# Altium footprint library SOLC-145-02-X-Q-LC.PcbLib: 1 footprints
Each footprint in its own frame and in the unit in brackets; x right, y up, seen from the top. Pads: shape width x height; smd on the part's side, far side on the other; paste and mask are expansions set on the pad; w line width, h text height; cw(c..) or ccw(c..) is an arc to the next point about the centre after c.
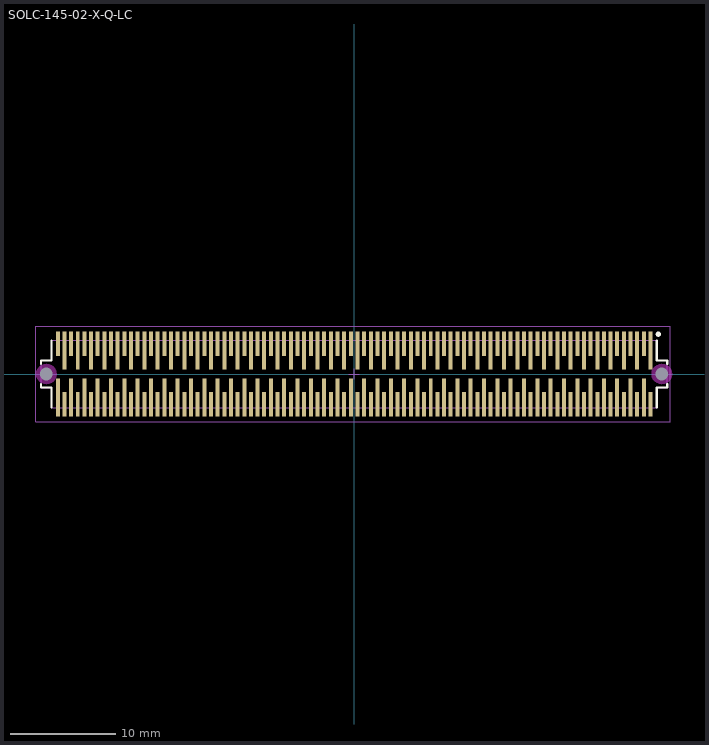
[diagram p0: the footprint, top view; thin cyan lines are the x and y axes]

## SOLC-145-02-X-Q-LC [mm] "1.27mm pitch, 180 pin, socket strip; 4 rows, w/locking clips, SMT"
height 4.62
pads (182):
  round 1 hole 1.2 unplated mask+0: 181(-29.337,0) 182(29.337,0)
  rect 0.38x2.36 smd mask+0: A1(27.622,2.885) A2(26.352,2.885) A3(25.082,2.885) A4(23.812,2.885) A5(22.543,2.885) A6(21.273,2.885) A7(20.002,2.885) A8(18.732,2.885) A9(17.462,2.885) A10(16.192,2.885) A11(14.922,2.885) A12(13.652,2.885) A13(12.383,2.885) A14(11.112,2.885) A15(9.842,2.885) A16(8.572,2.885) A17(7.302,2.885) A18(6.032,2.885) A19(4.763,2.885) A20(3.492,2.885) A21(2.222,2.885) A22(0.953,2.885) A23(-0.318,2.885) A24(-1.587,2.885) A25(-2.857,2.885) A26(-4.127,2.885) A27(-5.397,2.885) A28(-6.667,2.885) A29(-7.938,2.885) A30(-9.207,2.885) A31(-10.477,2.885) A32(-11.747,2.885) A33(-13.018,2.885) A34(-14.287,2.885) A35(-15.557,2.885) A36(-16.828,2.885) A37(-18.098,2.885) A38(-19.367,2.885) A39(-20.637,2.885) A40(-21.907,2.885) A41(-23.177,2.885) A42(-24.447,2.885) A43(-25.717,2.885) A44(-26.987,2.885) A45(-28.258,2.885) D1(28.258,-2.885) D2(26.987,-2.885) D3(25.717,-2.885) D4(24.447,-2.885) D5(23.177,-2.885) D6(21.907,-2.885) D7(20.637,-2.885) D8(19.367,-2.885) D9(18.098,-2.885) D10(16.828,-2.885) D11(15.557,-2.885) D12(14.287,-2.885) D13(13.018,-2.885) D14(11.747,-2.885) D15(10.477,-2.885) D16(9.207,-2.885) D17(7.938,-2.885) D18(6.667,-2.885) D19(5.397,-2.885) D20(4.127,-2.885) D21(2.857,-2.885) D22(1.587,-2.885) D23(0.318,-2.885) D24(-0.953,-2.885) D25(-2.222,-2.885) D26(-3.492,-2.885) D27(-4.763,-2.885) D28(-6.032,-2.885) D29(-7.302,-2.885) D30(-8.572,-2.885) D31(-9.842,-2.885) D32(-11.112,-2.885) D33(-12.383,-2.885) D34(-13.652,-2.885) D35(-14.922,-2.885) D36(-16.192,-2.885) D37(-17.462,-2.885) D38(-18.732,-2.885) D39(-20.002,-2.885) D40(-21.273,-2.885) D41(-22.543,-2.885) D42(-23.812,-2.885) D43(-25.082,-2.885) D44(-26.352,-2.885) D45(-27.622,-2.885)
  rect 0.38x3.63 smd mask+0: B1(28.258,2.25) B2(26.987,2.25) B3(25.717,2.25) B4(24.447,2.25) B5(23.177,2.25) B6(21.907,2.25) B7(20.637,2.25) B8(19.367,2.25) B9(18.098,2.25) B10(16.828,2.25) B11(15.557,2.25) B12(14.287,2.25) B13(13.018,2.25) B14(11.747,2.25) B15(10.477,2.25) B16(9.207,2.25) B17(7.938,2.25) B18(6.667,2.25) B19(5.397,2.25) B20(4.127,2.25) B21(2.857,2.25) B22(1.587,2.25) B23(0.318,2.25) B24(-0.953,2.25) B25(-2.222,2.25) B26(-3.492,2.25) B27(-4.763,2.25) B28(-6.032,2.25) B29(-7.302,2.25) B30(-8.572,2.25) B31(-9.842,2.25) B32(-11.112,2.25) B33(-12.383,2.25) B34(-13.652,2.25) B35(-14.922,2.25) B36(-16.192,2.25) B37(-17.462,2.25) B38(-18.732,2.25) B39(-20.002,2.25) B40(-21.273,2.25) B41(-22.543,2.25) B42(-23.812,2.25) B43(-25.082,2.25) B44(-26.352,2.25) B45(-27.622,2.25) C1(27.622,-2.25) C2(26.352,-2.25) C3(25.082,-2.25) C4(23.812,-2.25) C5(22.543,-2.25) C6(21.273,-2.25) C7(20.002,-2.25) C8(18.732,-2.25) C9(17.462,-2.25) C10(16.192,-2.25) C11(14.922,-2.25) C12(13.652,-2.25) C13(12.383,-2.25) C14(11.112,-2.25) C15(9.842,-2.25) C16(8.572,-2.25) C17(7.302,-2.25) C18(6.032,-2.25) C19(4.763,-2.25) C20(3.492,-2.25) C21(2.222,-2.25) C22(0.953,-2.25) C23(-0.318,-2.25) C24(-1.587,-2.25) C25(-2.857,-2.25) C26(-4.127,-2.25) C27(-5.397,-2.25) C28(-6.667,-2.25) C29(-7.938,-2.25) C30(-9.207,-2.25) C31(-10.477,-2.25) C32(-11.747,-2.25) C33(-13.018,-2.25) C34(-14.287,-2.25) C35(-15.557,-2.25) C36(-16.828,-2.25) C37(-18.098,-2.25) C38(-19.367,-2.25) C39(-20.637,-2.25) C40(-21.907,-2.25) C41(-23.177,-2.25) C42(-24.447,-2.25) C43(-25.717,-2.25) C44(-26.987,-2.25) C45(-28.258,-2.25)
Top Overlay:
  circle w0.25: c29,3.8 r0.125
  lines w0.2: -29.85,-0.95 -29.85,-1.3 -28.85,-1.3 -28.85,-3.2 ; -29.85,0.95 -29.85,1.3 -28.85,1.3 -28.85,3.2 ; 28.85,-3.2 28.85,-1.3 29.85,-1.3 29.85,-0.95 ; 28.85,3.2 28.85,1.3 29.85,1.3 29.85,0.95
Keep-Out Layer:
  pour cut-out: 30.32,0 30.287,0.255 30.189,0.492 30.032,0.695 29.829,0.852 29.592,0.95 29.337,0.983 29.082,0.95 28.845,0.852 28.642,0.695 28.485,0.492 28.387,0.255 28.354,0 28.387,-0.255 28.485,-0.492 28.642,-0.695 28.845,-0.852 29.082,-0.95 29.337,-0.983 29.592,-0.95 29.829,-0.852 30.032,-0.695 30.189,-0.492 30.287,-0.255
  pour cut-out: -28.354,0 -28.387,0.255 -28.485,0.492 -28.642,0.695 -28.845,0.852 -29.082,0.95 -29.337,0.983 -29.592,0.95 -29.829,0.852 -30.032,0.695 -30.189,0.492 -30.287,0.255 -30.32,0 -30.287,-0.255 -30.189,-0.492 -30.032,-0.695 -29.829,-0.852 -29.592,-0.95 -29.337,-0.983 -29.082,-0.95 -28.845,-0.852 -28.642,-0.695 -28.485,-0.492 -28.387,-0.255
Mechanical 12:
  lines w0.001: -29.85,-1.3 -29.85,1.3 -28.85,1.3 -28.85,3.2 28.85,3.2 28.85,1.3 29.85,1.3 29.85,-1.3 28.85,-1.3 28.85,-3.2 -28.85,-3.2 -28.85,-1.3 -29.85,-1.3
Mechanical 13:
  lines w0.1: -29.85,-1.3 -29.85,1.3 -28.85,1.3 -28.85,3.2 28.85,3.2 28.85,1.3 29.85,1.3 29.85,-1.3 28.85,-1.3 28.85,-3.2 -28.85,-3.2 -28.85,-1.3 -29.85,-1.3
  text ".Designator" at 0.127,-0.127 h1.52
Mechanical 15:
  lines w0.05: -0.5,0 0.5,0 ; 0,-0.5 0,0.5 ; -30.35,-4.55 -30.35,4.55 30.15,4.55 30.15,-4.55 -30.35,-4.55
